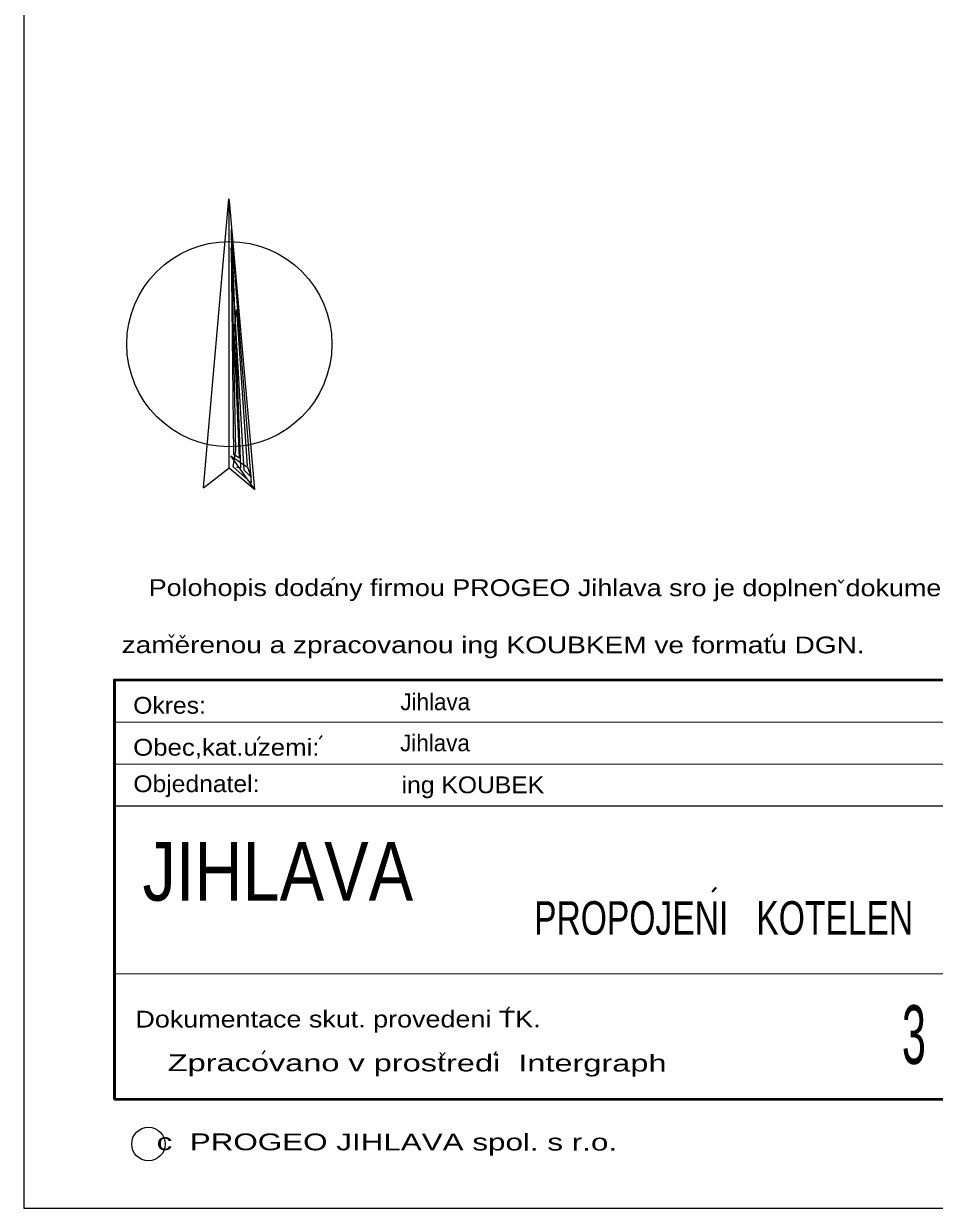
# Model space of a CAD drawing. Extents: x -670514 to -669423, y -1130798 to -1130123.
# Drawn here: x -670513.6 to -670470.2, y -1130676.8 to -1130620.2 of the extents above; entities that cross this region are included whole.
import ezdxf
from ezdxf.enums import TextEntityAlignment as Align

# ---------------------------------------------------------------- set-up
doc = ezdxf.new("R2010")
doc.units = 0
doc.header["$LTSCALE"] = 0.24
doc.layers.add('60', color=7, linetype='Continuous', lineweight=13)
doc.layers.add('61', color=7, linetype='Continuous', lineweight=13)

msp = doc.modelspace()

# ---------------------------------------------------------------- linework, layer by layer
at = {"layer": '60'}
msp.add_lwpolyline([(-670513.627, -1130676.756), (-670103.627, -1130676.756), (-670103.627, -1130389.756), (-670513.627, -1130389.756)], close=True, dxfattribs=at)
at = {"layer": '61'}
for p, q in [((-670505.05, -1130642.38), (-670503.845, -1130628.602)), ((-670503.815, -1130641.427), (-670503.815, -1130628.596)), ((-670502.604, -1130642.467), (-670503.811, -1130628.689)), ((-670498.783, -1130646.644), (-670498.916, -1130646.795)), ((-670474.763, -1130646.778), (-670474.63, -1130646.927)), ((-670474.496, -1130646.776), (-670474.63, -1130646.927)), ((-670506.706, -1130649.384), (-670506.574, -1130649.532)), ((-670506.442, -1130649.382), (-670506.574, -1130649.532)), ((-670506.179, -1130649.417), (-670506.047, -1130649.565)), ((-670505.915, -1130649.415), (-670506.047, -1130649.565)), ((-670477.88, -1130649.355), (-670478.014, -1130649.503)), ((-670509.303, -1130653.563), (-670469.298, -1130653.55)), ((-670502.464, -1130654.421), (-670502.345, -1130654.249)), ((-670499.506, -1130654.376), (-670499.391, -1130654.199)), ((-670509.303, -1130655.564), (-670469.303, -1130655.553)), ((-670509.3, -1130657.559), (-670469.3, -1130657.551)), ((-670509.3, -1130665.563), (-670469.302, -1130665.553)), ((-670490.567, -1130667.317), (-670490.451, -1130667.14)), ((-670502.224, -1130669.406), (-670502.109, -1130669.231)), ((-670493.775, -1130669.322), (-670493.642, -1130669.472)), ((-670493.509, -1130669.324), (-670493.642, -1130669.472)), ((-670491.183, -1130669.447), (-670491.068, -1130669.27))]:
    msp.add_line(p, q, dxfattribs=at)
at = {"layer": '61', "lineweight": 40}
msp.add_line((-670480.777, -1130661.654), (-670480.591, -1130661.449), dxfattribs=at)
at = {"layer": '61'}
for points in [[(-670503.732, -1130630.062), (-670502.772, -1130642.143), (-670503.631, -1130641.385), (-670503.504, -1130640.601), (-670503.706, -1130630.163), (-670503.277, -1130641.435), (-670503.479, -1130641.41)], [(-670505.05, -1130642.38), (-670503.815, -1130641.427), (-670502.604, -1130642.467), (-670503.75, -1130640.855), (-670502.943, -1130641.405), (-670502.777, -1130641.886), (-670503.108, -1130641.542), (-670503.732, -1130630.932), (-670503.622, -1130640.787), (-670503.328, -1130640.958), (-670503.585, -1130634.95), (-670503.475, -1130633.885), (-670502.961, -1130641.336)]]:
    msp.add_lwpolyline(points, dxfattribs=at)
at = {"layer": '61', "lineweight": 53}
msp.add_lwpolyline([(-670509.297, -1130671.564), (-670449.3, -1130671.545), (-670449.301, -1130651.548), (-670509.3, -1130651.56)], close=True, dxfattribs=at)
at = {"layer": '61'}
for centre, radius in [((-670503.815, -1130635.532), 4.8953), ((-670507.6744, -1130673.6919), 0.8)]:
    msp.add_circle(centre, radius, dxfattribs=at)

# ---------------------------------------------------------------- texts
for s, height, rotation, width, p in [('Polohopis dodany firmou PROGEO Jihlava sro je doplnen dokumentaci TK', 0.8, 359.983, 1.2, (-670486.3971, -1130647.5527)), ('zamerenou a zpracovanou ing KOUBKEM ve formatu DGN.', 0.8, 359.983, 1.25, (-670491.2266, -1130650.2773)), ('JIHLAVA', 2.8, 0.009, 0.85, (-670501.4997, -1130662.0809)), ('3', 2.8, 0.009, 0.55, (-670471.1462, -1130669.8679)), ('Zpracovano v prostredi  Intergraph', 0.8, 359.948, 1.45, (-670494.8529, -1130670.2231)), ('c  PROGEO JIHLAVA spol. s r.o.', 0.8, 359.948, 1.4, (-670496.2974, -1130673.9926))]:
    msp.add_text(s, height=height, rotation=rotation, dxfattribs=dict(at, width=width)).set_placement(p, align=Align.CENTER)
for s, height, rotation, width, p in [('Okres:', 0.8, 0.014, 1.1, (-670508.4, -1130653.161)), ('Obec,kat.uzemi:', 0.8, 0.014, 1.15, (-670508.403, -1130655.164)), ('Objednatel:', 0.8, 0.014, 1.1, (-670508.394, -1130656.904)), ('ing KOUBEK', 0.8, 0.015, 1.1, (-670495.594, -1130656.956)), ('PROPOJENI   KOTELEN', 1.599, 0.009, 0.75, (-670489.272, -1130663.705)), ('Dokumentace skut. provedeni TK.', 0.8, 0.015, 1.2, (-670508.295, -1130668.132))]:
    msp.add_text(s, height=height, rotation=rotation, dxfattribs=dict(at, width=width)).set_placement(p)
for p in [(-670495.652, -1130652.995), (-670495.665, -1130654.954)]:
    msp.add_text('Jihlava', height=0.8, rotation=0.015, dxfattribs=at).set_placement(p)

doc.saveas('drawing.dxf')
